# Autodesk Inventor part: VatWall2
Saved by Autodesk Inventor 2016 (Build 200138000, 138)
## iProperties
Created: 2015-11
Part Number: VatWall2
Material: Generic
Document SubType Name: Modeling
Designer: John
Density: 1 g/cm^3
Appearance: Default
Author: John
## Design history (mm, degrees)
feature "Base1"
body "Solid1"
